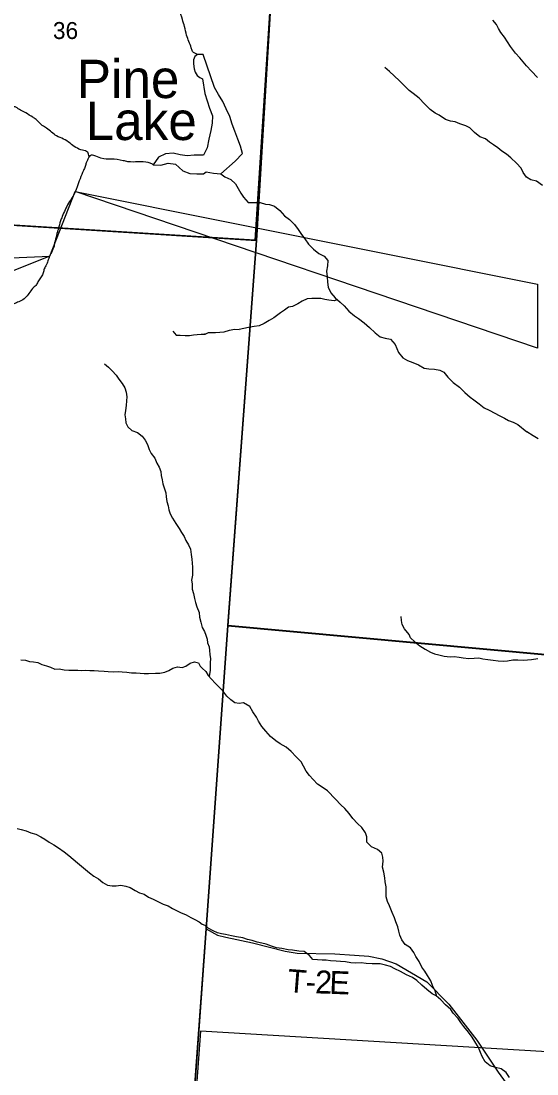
# Model space of a CAD drawing. Extents: x -13.1 to 43.1, y 0 to 22.
# Drawn here: x 6.242 to 7.517, y 14.849 to 17.45 of the extents above; entities that cross this region are included whole.
import ezdxf

# ---------------------------------------------------------------- set-up
doc = ezdxf.new("R2010")
doc.units = 0
for name, color, linetype in [('GM_X_Corporation', 7, 'Continuous'), ('GM_X_Minor_Lake', 7, 'Continuous'), ('GM_X_Minor_Lake_Text', 7, 'Continuous'), ('GM_X_Minor_River', 7, 'Continuous'), ('GM_X_Section_Text', 7, 'Continuous'), ('GM_X_Township_Road', 7, 'Continuous'), ('GM_X_Township_Road_Text', 7, 'Continuous'), ('SH_Text', 7, 'Continuous')]:
    doc.layers.add(name, color=color, linetype=linetype)

msp = doc.modelspace()

# ---------------------------------------------------------------- linework, layer by layer
at = {"layer": 'GM_X_Corporation'}
for points in [[(7.0807, 20.9), (2.1, 20.9), (2.1, 14.1), (6.6193, 14.1), (6.6994, 15.2069), (6.7531, 15.956), (6.8236, 16.9075), (6.9509, 19.0179), (7.0108, 19.8446), (7.0164, 19.8954), (7.0617, 20.6133)], [(7.0804, 20.9), (2.1, 20.9), (2.1, 14.1), (6.619, 14.1), (6.6992, 15.2074), (6.7528, 15.9566), (6.8234, 16.908), (6.8365, 17.1257), (6.9507, 19.0184), (6.9616, 19.1692), (7.0106, 19.8452), (7.0162, 19.896), (7.0615, 20.6138)], [(7.0804, 20.9), (2.1, 20.9), (2.1, 17.2152), (2.1437, 17.2135), (2.8442, 17.1637), (3.8328, 17.0966), (4.4304, 17.0575), (6.8234, 16.908), (6.8365, 17.1257), (6.9507, 19.0184), (6.9616, 19.1692), (7.0106, 19.8452), (7.0162, 19.896), (7.0615, 20.6138)], [(8.9, 15.7487), (8.9, 20.9), (7.0804, 20.9), (7.0615, 20.6138), (7.0162, 19.896), (7.0106, 19.8452), (6.9616, 19.1692), (6.9507, 19.0184), (6.8365, 17.1257), (6.8234, 16.908), (6.7528, 15.9566), (7.8612, 15.855), (8.7782, 15.7572)], [(8.9, 15.7487), (8.9, 20.9), (7.0804, 20.9), (7.0615, 20.6138), (7.0162, 19.896), (7.0106, 19.8452), (6.9616, 19.1692), (6.9507, 19.0184), (6.8365, 17.1257), (6.8234, 16.908), (6.7528, 15.9566), (7.8612, 15.855), (8.7782, 15.7572)], [(8.9, 15.7481), (8.9, 20.9), (7.0807, 20.9), (7.0617, 20.6133), (7.0164, 19.8954), (7.0108, 19.8446), (6.9509, 19.0179), (6.8236, 16.9075), (6.7531, 15.956), (7.8614, 15.8545), (8.7784, 15.7567)], [(5.8912, 17.9717), (6.8837, 17.9051), (6.8193, 16.9086), (5.8169, 16.9715)], [(2.1, 17.2152), (2.1, 14.1), (6.619, 14.1), (6.6992, 15.2074), (6.7528, 15.9566), (6.8234, 16.908), (4.4304, 17.0575), (3.8328, 17.0966), (2.8442, 17.1637), (2.1437, 17.2135)], [(6.619, 14.1), (8.9, 14.1), (8.9, 15.7487), (8.7782, 15.7572), (7.8612, 15.855), (6.7528, 15.9566), (6.6992, 15.2074)], [(6.619, 14.1), (8.9, 14.1), (8.9, 15.7487), (8.7782, 15.7572), (7.8612, 15.855), (6.7528, 15.9566), (6.6992, 15.2074)], [(6.6193, 14.1), (8.9, 14.1), (8.9, 15.7481), (8.7784, 15.7567), (7.8614, 15.8545), (6.7531, 15.956), (6.6994, 15.2069)], [(6.623, 14.1), (7.7024, 14.1), (7.7762, 14.8894), (6.6851, 14.9543)]]:
    msp.add_lwpolyline(points, close=True, dxfattribs=at)
at = {"layer": 'GM_X_Minor_Lake'}
for points in [[(6.6918, 17.367), (6.6784, 17.3673), (6.6715, 17.3625), (6.6684, 17.3542), (6.6683, 17.3439), (6.67, 17.3321), (6.6722, 17.3238), (6.6774, 17.3154), (6.6834, 17.3103), (6.6905, 17.3068)], [(6.6926, 17.0727), (6.6996, 17.0777), (6.7177, 17.0738), (6.7359, 17.0721), (6.7709, 17.1037), (6.7891, 17.1225), (6.784, 17.1408), (6.7773, 17.1582), (6.7699, 17.178), (6.7639, 17.1955), (6.758, 17.2145), (6.7491, 17.2327), (6.7409, 17.251), (6.7296, 17.2685), (6.7199, 17.286), (6.6918, 17.367)], [(6.6905, 17.3068), (6.6964, 17.271), (6.7016, 17.2528), (6.7075, 17.2345), (6.7149, 17.2155), (6.714, 17.1974), (6.7109, 17.1799), (6.7062, 17.158), (6.7023, 17.1368), (6.6927, 17.119)], [(6.6927, 17.119), (6.6699, 17.1184), (6.6525, 17.117), (6.6351, 17.1195), (6.6177, 17.1234), (6.5988, 17.122), (6.5813, 17.1138), (6.5683, 17.095), (6.5872, 17.0941), (6.6054, 17.0992), (6.6236, 17.096), (6.6416, 17.0799), (6.659, 17.0737), (6.6764, 17.0728), (6.6926, 17.0727)]]:
    msp.add_lwpolyline(points, dxfattribs=at)
at = {"layer": 'GM_X_Minor_River'}
for p, q in [((7.4166, 17.4411), (7.408, 17.4518)), ((7.4218, 17.4316), (7.4166, 17.4411)), ((7.4275, 17.4213), (7.4218, 17.4316)), ((7.4365, 17.4099), (7.4275, 17.4213)), ((7.4439, 17.3985), (7.4365, 17.4099)), ((7.4511, 17.3874), (7.4439, 17.3985)), ((7.4638, 17.371), (7.4511, 17.3874)), ((7.4747, 17.3592), (7.4638, 17.371)), ((7.4822, 17.3489), (7.4747, 17.3592)), ((7.1526, 17.3249), (7.1409, 17.3352)), ((7.1635, 17.3146), (7.1526, 17.3249)), ((7.4909, 17.3394), (7.4822, 17.3489)), ((7.5033, 17.326), (7.4909, 17.3394)), ((7.5179, 17.3104), (7.5033, 17.326)), ((7.1774, 17.302), (7.1635, 17.3146)), ((7.1887, 17.2909), (7.1774, 17.302)), ((7.2011, 17.2787), (7.1887, 17.2909)), ((7.2109, 17.2706), (7.2011, 17.2787)), ((7.2256, 17.2592), (7.2109, 17.2706)), ((7.2391, 17.2451), (7.2256, 17.2592)), ((7.253, 17.2317), (7.2391, 17.2451)), ((7.2651, 17.2225), (7.253, 17.2317)), ((7.2749, 17.2171), (7.2651, 17.2225)), ((7.2903, 17.2064), (7.2749, 17.2171)), ((7.3032, 17.2022), (7.2903, 17.2064)), ((7.3145, 17.2013), (7.3032, 17.2022)), ((7.3262, 17.1959), (7.3145, 17.2013)), ((7.341, 17.1913), (7.3262, 17.1959)), ((7.3511, 17.1859), (7.341, 17.1913)), ((7.362, 17.1745), (7.3511, 17.1859)), ((7.3756, 17.1641), (7.362, 17.1745)), ((7.3892, 17.1587), (7.3756, 17.1641)), ((7.3994, 17.1511), (7.3892, 17.1587)), ((7.4092, 17.1438), (7.3994, 17.1511)), ((7.4201, 17.1365), (7.4092, 17.1438)), ((7.4299, 17.1285), (7.4201, 17.1365)), ((7.4416, 17.1212), (7.4299, 17.1285)), ((7.4521, 17.1124), (7.4416, 17.1212)), ((7.466, 17.0991), (7.4521, 17.1124)), ((7.4777, 17.0861), (7.466, 17.0991)), ((7.4829, 17.0754), (7.4777, 17.0861)), ((7.4908, 17.0644), (7.4829, 17.0754)), ((7.5013, 17.0579), (7.4908, 17.0644)), ((7.5153, 17.0544), (7.5013, 17.0579)), ((7.53, 17.0437), (7.5153, 17.0544)), ((6.803, 17.0014), (6.8329, 17.0019)), ((6.8329, 17.0019), (6.8461, 16.9973)), ((6.8461, 16.9973), (6.8559, 16.9964)), ((6.8559, 16.9964), (6.8684, 16.993)), ((6.8684, 16.993), (6.8812, 16.9822)), ((6.8812, 16.9822), (6.8929, 16.9685)), ((6.8929, 16.9685), (6.9053, 16.9593)), ((6.9053, 16.9593), (6.9173, 16.9471)), ((6.9173, 16.9471), (6.9263, 16.9349)), ((6.9263, 16.9349), (6.9346, 16.9227)), ((6.9346, 16.9227), (6.9428, 16.9121)), ((6.9428, 16.9121), (6.9526, 16.8991)), ((6.9526, 16.8991), (6.9642, 16.8861)), ((6.9642, 16.8861), (6.9778, 16.8754)), ((6.9778, 16.8754), (6.9906, 16.8693)), ((6.9906, 16.8693), (7, 16.8582)), ((7, 16.8582), (6.9995, 16.8449)), ((6.9995, 16.8449), (6.9971, 16.8317)), ((6.9971, 16.8317), (6.9982, 16.818)), ((6.9982, 16.818), (6.9988, 16.8047)), ((6.9988, 16.8047), (7.0006, 16.7922)), ((7.0006, 16.7922), (7.0074, 16.7789)), ((7.0074, 16.7789), (7.0183, 16.7659)), ((6.9364, 16.7577), (6.9261, 16.7513)), ((6.9486, 16.7633), (6.9364, 16.7577)), ((6.9603, 16.7648), (6.9486, 16.7633)), ((6.9826, 16.7646), (6.9603, 16.7648)), ((6.9928, 16.7619), (6.9826, 16.7646)), ((7.0027, 16.7603), (6.9928, 16.7619)), ((7.0155, 16.7587), (7.0027, 16.7603)), ((7.0234, 16.7615), (7.0155, 16.7587)), ((7.0183, 16.7659), (7.0303, 16.7556)), ((7.0303, 16.7556), (7.0401, 16.7464)), ((6.8832, 16.7289), (6.8668, 16.7165)), ((6.8927, 16.7356), (6.8832, 16.7289)), ((6.9026, 16.7428), (6.8927, 16.7356)), ((6.9124, 16.745), (6.9026, 16.7428)), ((6.9261, 16.7513), (6.9124, 16.745)), ((7.0401, 16.7464), (7.0521, 16.7335)), ((7.0521, 16.7335), (7.0656, 16.7216)), ((6.8428, 16.7026), (6.8307, 16.6973)), ((6.8554, 16.7105), (6.8428, 16.7026)), ((6.8668, 16.7165), (6.8554, 16.7105)), ((7.0656, 16.7216), (7.0754, 16.7147)), ((7.0754, 16.7147), (7.0898, 16.704)), ((7.0898, 16.704), (7.1029, 16.6925)), ((6.8041, 16.6926), (6.781, 16.6877)), ((6.8182, 16.6955), (6.8041, 16.6926)), ((6.8307, 16.6973), (6.8182, 16.6955)), ((7.1029, 16.6925), (7.1172, 16.6796)), ((7.1172, 16.6796), (7.1289, 16.67)), ((7.1289, 16.67), (7.1414, 16.6669)), ((7.1414, 16.6669), (7.1546, 16.6641)), ((7.1546, 16.6641), (7.1662, 16.6508)), ((7.1662, 16.6508), (7.1703, 16.6413)), ((7.1703, 16.6413), (7.1748, 16.6314)), ((7.1748, 16.6314), (7.1849, 16.6177)), ((7.1849, 16.6177), (7.197, 16.6111)), ((7.197, 16.6111), (7.2102, 16.6061)), ((7.2102, 16.6061), (7.2242, 16.6007)), ((7.2242, 16.6007), (7.2382, 16.5927)), ((7.2382, 16.5927), (7.2495, 16.5911)), ((7.2495, 16.5911), (7.2631, 16.5902)), ((7.2631, 16.5902), (7.2764, 16.5875)), ((7.2764, 16.5875), (7.2862, 16.5825)), ((7.2862, 16.5825), (7.2963, 16.5703)), ((7.2963, 16.5703), (7.3098, 16.5569)), ((7.3098, 16.5569), (7.3249, 16.5454)), ((7.3249, 16.5454), (7.3384, 16.5321)), ((7.3384, 16.5321), (7.3512, 16.5206)), ((7.3512, 16.5206), (7.361, 16.5145)), ((7.361, 16.5145), (7.3735, 16.5045)), ((7.3735, 16.5045), (7.3863, 16.4946)), ((7.3863, 16.4946), (7.3987, 16.4885)), ((7.3987, 16.4885), (7.4123, 16.4812)), ((7.4123, 16.4812), (7.4229, 16.4754)), ((7.4229, 16.4754), (7.4361, 16.4692)), ((7.4361, 16.4692), (7.4466, 16.4635)), ((7.4466, 16.4635), (7.4576, 16.4592)), ((7.4576, 16.4592), (7.4693, 16.4535)), ((7.4693, 16.4535), (7.4915, 16.4352)), ((7.5072, 16.4255), (7.4915, 16.4352)), ((7.5192, 16.4175), (7.5072, 16.4255)), ((7.182, 15.9694), (7.1813, 15.9788)), ((7.1835, 15.9591), (7.182, 15.9694)), ((7.1891, 15.9481), (7.1835, 15.9591)), ((7.2007, 15.9344), (7.1891, 15.9481)), ((7.2046, 15.9264), (7.2007, 15.9344))]:
    msp.add_line(p, q, dxfattribs=at)
for points in [[(6.7359, 17.0721), (6.7457, 17.0651), (6.7605, 17.0587), (6.7719, 17.0481), (6.7787, 17.036), (6.7848, 17.025), (6.792, 17.0152), (6.803, 17.0014)], [(6.6174, 16.6842), (6.6255, 16.6742), (6.6353, 16.674), (6.6474, 16.673), (6.6584, 16.6732), (6.6679, 16.6746), (6.6774, 16.6755), (6.6872, 16.6765), (6.697, 16.676), (6.6955, 16.6764)], [(6.697, 16.676), (6.7049, 16.6807), (6.7223, 16.6807), (6.7333, 16.6812), (6.7439, 16.6823), (6.7567, 16.6862), (6.7692, 16.6888), (6.781, 16.6877)], [(6.4481, 16.6029), (6.4578, 16.5947), (6.4675, 16.5855), (6.4768, 16.5751), (6.4838, 16.5651), (6.4923, 16.5547), (6.4982, 16.544), (6.5018, 16.5333), (6.5031, 16.5219), (6.5026, 16.5113), (6.502, 16.5003), (6.4999, 16.4875), (6.4986, 16.4769), (6.5, 16.4674), (6.5006, 16.4571), (6.5057, 16.4472), (6.5158, 16.4387)], [(6.5158, 16.4387), (6.5296, 16.4336), (6.5417, 16.4247), (6.5491, 16.4148), (6.5543, 16.4037), (6.5587, 16.3915), (6.5639, 16.3819), (6.5725, 16.37), (6.5773, 16.3574), (6.5833, 16.3475), (6.5873, 16.3368), (6.588, 16.3269), (6.5905, 16.3166), (6.5923, 16.3064), (6.5963, 16.2942), (6.5996, 16.2842), (6.601, 16.2747), (6.602, 16.2633), (6.6057, 16.2526), (6.6075, 16.2428), (6.6108, 16.2325), (6.6159, 16.2218), (6.6249, 16.2083), (6.6327, 16.1965), (6.6387, 16.1865), (6.645, 16.1766), (6.6495, 16.167), (6.6562, 16.1559), (6.6606, 16.1452), (6.6627, 16.1323), (6.6641, 16.1209), (6.6648, 16.111), (6.6658, 16.1007), (6.6656, 16.0905), (6.6659, 16.081), (6.6635, 16.0689), (6.6645, 16.0594), (6.6647, 16.0468), (6.668, 16.0354), (6.6709, 16.0232), (6.6731, 16.0133), (6.6764, 16.0026), (6.6823, 15.9885), (6.6826, 15.9769), (6.686, 15.9652), (6.6895, 15.9514)], [(6.6895, 15.9514), (6.6955, 15.9419), (6.699, 15.9325), (6.7015, 15.923), (6.7028, 15.9135), (6.7071, 15.904), (6.7076, 15.8945), (6.7089, 15.885), (6.7102, 15.8747), (6.7093, 15.8652), (6.7093, 15.8553), (6.7097, 15.8458), (6.7076, 15.8363), (6.7066, 15.8305)], [(7.2046, 15.9264), (7.2148, 15.9162), (7.2272, 15.9067), (7.2401, 15.8979), (7.2537, 15.8904), (7.2636, 15.8866), (7.2738, 15.8839), (7.2874, 15.8805), (7.3018, 15.8793), (7.3124, 15.8801), (7.3241, 15.8786), (7.3343, 15.8766), (7.3483, 15.8755), (7.3612, 15.8762), (7.3733, 15.8766), (7.3831, 15.8743), (7.3952, 15.8728), (7.4081, 15.8709), (7.4206, 15.869), (7.4338, 15.8686), (7.4437, 15.8694), (7.4573, 15.8716), (7.4694, 15.8716), (7.4827, 15.8709), (7.4933, 15.872), (7.5031, 15.8727), (7.519, 15.8754)], [(6.2415, 15.8722), (6.2529, 15.871), (6.2627, 15.8674), (6.2726, 15.8673), (6.2832, 15.8656), (6.2934, 15.8606), (6.3048, 15.8566), (6.315, 15.8535), (6.3256, 15.8491), (6.3362, 15.8494), (6.3487, 15.8469), (6.3598, 15.846), (6.3704, 15.8459), (6.3826, 15.8465), (6.3924, 15.8456), (6.4019, 15.8459), (6.4118, 15.8458), (6.4225, 15.8452), (6.4338, 15.8443), (6.4475, 15.8438), (6.4574, 15.8429), (6.4695, 15.842), (6.4817, 15.8426), (6.4923, 15.8421), (6.5037, 15.8412), (6.5147, 15.8399), (6.5265, 15.8397), (6.5364, 15.8388), (6.5466, 15.8383), (6.5573, 15.8382), (6.5744, 15.8387), (6.5847, 15.8386), (6.5972, 15.8411), (6.6072, 15.8455), (6.6175, 15.8511), (6.6286, 15.8544), (6.6399, 15.8527), (6.6495, 15.856), (6.6595, 15.8638), (6.6705, 15.8671), (6.6807, 15.8643), (6.6847, 15.8562), (6.6892, 15.851)], [(6.6892, 15.851), (6.699, 15.8428), (6.7041, 15.8333), (6.7128, 15.8238), (6.7218, 15.8143), (6.7233, 15.8122)], [(7.2691, 15.04), (7.2654, 15.0544), (7.2586, 15.0673), (7.2541, 15.079), (7.2465, 15.0919), (7.2393, 15.1026), (7.2325, 15.1128), (7.2253, 15.1264), (7.217, 15.139), (7.2128, 15.1488), (7.2038, 15.1606), (7.1913, 15.1689), (7.1826, 15.1799), (7.1777, 15.1917), (7.1758, 15.2016), (7.1731, 15.2118), (7.1682, 15.2247), (7.1644, 15.2345), (7.1588, 15.2474), (7.152, 15.2641), (7.1474, 15.2744), (7.1444, 15.2861), (7.1437, 15.2971), (7.1444, 15.3111), (7.1418, 15.3237), (7.1407, 15.3331), (7.138, 15.3472), (7.135, 15.3597), (7.1365, 15.3748), (7.1361, 15.3843), (7.1335, 15.3946), (7.1225, 15.4033), (7.1081, 15.4101), (7.096, 15.4211), (7.0961, 15.4348), (7.0934, 15.4442), (7.084, 15.4575), (7.073, 15.4674), (7.0616, 15.4795), (7.0529, 15.492), (7.0416, 15.5042), (7.0325, 15.5137), (7.0193, 15.5277), (6.9992, 15.5478), (6.9886, 15.5554), (6.9746, 15.5645), (6.9637, 15.5759), (6.955, 15.5858), (6.9467, 15.5964), (6.9402, 15.6089), (6.9342, 15.6195), (6.9217, 15.6324), (6.9096, 15.6457), (6.8967, 15.6559), (6.882, 15.6643), (6.8714, 15.6715), (6.8585, 15.6825), (6.8468, 15.6954), (6.837, 15.7068), (6.829, 15.7201), (6.8234, 15.7303), (6.815, 15.7436), (6.8075, 15.7565), (6.792, 15.7652), (6.7806, 15.7637), (6.7704, 15.7652), (6.7602, 15.7728), (6.7503, 15.7823), (6.7409, 15.7956), (6.7284, 15.8077), (6.7233, 15.8122)], [(6.2322, 15.4554), (6.2424, 15.4526), (6.2546, 15.449), (6.2663, 15.4447), (6.2784, 15.4411), (6.2909, 15.4349), (6.3007, 15.4291), (6.312, 15.4213), (6.3233, 15.4147), (6.335, 15.4073), (6.3486, 15.3973), (6.3599, 15.3888), (6.3711, 15.3795), (6.3813, 15.3707), (6.3911, 15.3618), (6.4012, 15.3541), (6.4114, 15.3456), (6.4223, 15.3375), (6.4333, 15.3305), (6.4438, 15.322), (6.4555, 15.3154), (6.4669, 15.3134), (6.4768, 15.3136), (6.4889, 15.3154), (6.5007, 15.3129), (6.512, 15.309), (6.5241, 15.302), (6.5347, 15.2966), (6.5464, 15.2926), (6.5566, 15.2856), (6.5683, 15.2802), (6.5804, 15.2751), (6.5933, 15.2681), (6.6054, 15.2637), (6.6163, 15.2575), (6.6261, 15.2525), (6.6359, 15.2478), (6.6499, 15.2415), (6.6616, 15.2349), (6.6718, 15.2306), (6.682, 15.2244), (6.6895, 15.2192), (6.6958, 15.2162)], [(7.0948, 15.1216), (7.0823, 15.1231), (7.0683, 15.1228), (7.0565, 15.1232), (7.044, 15.1254), (7.0312, 15.1262), (7.0202, 15.127), (7.0062, 15.1285), (6.9956, 15.13), (6.9858, 15.1297), (6.9748, 15.1308), (6.9627, 15.1316), (6.9544, 15.1414), (6.9419, 15.1509), (6.9283, 15.1517), (6.9131, 15.1544), (6.9018, 15.1555), (6.8863, 15.1589), (6.8734, 15.1604), (6.8609, 15.1646), (6.8473, 15.1696), (6.8367, 15.1715), (6.8257, 15.1745), (6.8128, 15.1787), (6.8019, 15.1806), (6.7901, 15.1848), (6.7746, 15.1874), (6.7618, 15.1897), (6.7474, 15.1931), (6.7372, 15.1947), (6.7273, 15.197), (6.7171, 15.2023), (6.7042, 15.2091), (6.6958, 15.2162)], [(7.4488, 14.8401), (7.4405, 14.8526), (7.4284, 14.8613), (7.414, 14.8647), (7.4008, 14.8685), (7.3887, 14.8788), (7.3811, 14.892), (7.3773, 14.9019), (7.372, 14.914), (7.363, 14.9292), (7.3565, 14.9394), (7.3471, 14.9516), (7.3357, 14.966), (7.3286, 14.9762), (7.3221, 14.9861), (7.3096, 14.9986), (7.3036, 15.0081), (7.2907, 15.0199), (7.279, 15.032), (7.2673, 15.0415), (7.2574, 15.0468), (7.2446, 15.0574), (7.2325, 15.0684), (7.2196, 15.0794), (7.2094, 15.0874), (7.1946, 15.0935), (7.1795, 15.1022), (7.1655, 15.1087), (7.1545, 15.114), (7.1424, 15.1178), (7.1296, 15.1205), (7.1197, 15.1212), (7.1095, 15.1208), (7.0948, 15.1216)]]:
    msp.add_lwpolyline(points, dxfattribs=at)
for points in [[(6.6784, 17.3673), (6.6659, 17.3751), (6.6626, 17.3839), (6.6511, 17.4147), (6.646, 17.4363), (6.6408, 17.4538), (6.6283, 17.5035), (6.6232, 17.5281), (6.618, 17.5449), (6.6108, 17.585), (6.6094, 17.6002), (6.6075, 17.6082), (6.6038, 17.6226), (6.6012, 17.6234), (6.6009, 17.6272), (6.5866, 17.6338), (6.5651, 17.6413), (6.5312, 17.6508), (6.5222, 17.6585), (6.4823, 17.6757), (6.4642, 17.6813), (6.4254, 17.6943), (6.4179, 17.7001), (6.3837, 17.7153), (6.3667, 17.7212), (6.3291, 17.7365), (6.3246, 17.7423), (6.2994, 17.7562), (6.2866, 17.764), (6.2734, 17.7695), (6.2471, 17.7823), (6.2343, 17.7882), (6.2162, 17.7922), (6.1872, 17.8043), (6.1767, 17.8117), (6.1669, 17.8171), (6.1489, 17.8313), (6.141, 17.8383), (6.123, 17.8495), (6.1128, 17.8568), (6.0997, 17.8623), (6.0673, 17.8783), (6.0409, 17.8866), (6.0346, 17.892), (6.0075, 17.9067), (5.9977, 17.9114), (5.9902, 17.9179), (5.9642, 17.9315), (5.9537, 17.9374), (5.9432, 17.9417), (5.9278, 17.9563), (5.9161, 17.9647), (5.9128, 17.9716), (5.8986, 17.9896), (5.8918, 17.9957), (5.887, 18.0049), (5.8746, 18.019), (5.8701, 18.0263), (5.8544, 18.0458)], [(6.4101, 17.1149), (6.4067, 17.1259), (6.3939, 17.1306), (6.3631, 17.148), (6.3469, 17.1585), (6.33, 17.1663), (6.3052, 17.1852), (6.2947, 17.1917), (6.2793, 17.2067), (6.2711, 17.2125), (6.2538, 17.223), (6.247, 17.2268), (6.241, 17.2296), (6.2293, 17.2369), (6.2218, 17.24), (6.2154, 17.2439), (6.2116, 17.2451), (6.209, 17.2463), (6.2015, 17.246), (6.1943, 17.2457), (6.1852, 17.2451), (6.1735, 17.2404), (6.1682, 17.2359), (6.1624, 17.2265), (6.1362, 17.2038), (6.1097, 17.1902), (6.1036, 17.1801), (6.074, 17.1522), (6.0588, 17.1418), (6.016, 17.1186), (6.0102, 17.1084), (5.9925, 17.1026), (5.9678, 17.0883), (5.953, 17.0805), (5.9492, 17.0741), (5.9336, 17.0558), (5.9249, 17.0454), (5.9222, 17.0371), (5.9129, 17.0138), (5.9114, 17.0044), (5.9109, 16.9976), (5.9105, 16.9824), (5.9134, 16.9771), (5.9142, 16.9726), (5.916, 16.9597), (5.9167, 16.954), (5.9181, 16.9411), (5.9185, 16.9377)], [(6.5683, 17.095), (6.5613, 17.0987), (6.5564, 17.1003), (6.5062, 17.1025), (6.4946, 17.105), (6.4644, 17.1088), (6.4395, 17.1114), (6.4101, 17.1149), (6.4089, 17.1122), (6.4032, 17.0998), (6.4005, 17.0908), (6.3962, 17.0806), (6.3805, 17.04), (6.3705, 17.0171), (6.3594, 17.0002), (6.3437, 16.9668), (6.3395, 16.9563), (6.3341, 16.9363), (6.3318, 16.9292), (6.3275, 16.9111), (6.3256, 16.9043), (6.3236, 16.8941), (6.3171, 16.8783), (6.314, 16.8723), (6.3094, 16.8599), (6.3075, 16.8546), (6.3021, 16.8426), (6.2994, 16.8374), (6.2971, 16.8279), (6.2853, 16.8085), (6.2799, 16.7987), (6.2731, 16.7916), (6.2548, 16.7684), (6.2434, 16.7595), (6.2305, 16.754), (6.2063, 16.7453), (6.1779, 16.7408), (6.173, 16.7371), (6.1617, 16.7335), (6.1496, 16.731), (6.1269, 16.7222), (6.1151, 16.7201), (6.1019, 16.7177)]]:
    msp.add_spline(points, degree=3, dxfattribs=at)
at = {"layer": 'GM_X_Township_Road'}
msp.add_lwpolyline([(6.6994, 15.2069), (6.7277, 15.1918), (6.7478, 15.187), (6.8135, 15.1728), (6.8943, 15.1522), (6.9242, 15.1469), (7.017, 15.1455), (7.0662, 15.1425), (7.1014, 15.1401), (7.1332, 15.1329), (7.1686, 15.1206), (7.2442, 15.0762), (7.2987, 15.0212), (7.3684, 14.9325), (7.4211, 14.8528), (7.4576, 14.8021)], dxfattribs=at)
at = {"layer": 'SH_Text'}
msp.add_line((6.3129, 16.8693), (6.3758, 17.0288), dxfattribs=at)
for points in [[(7.5178, 16.6422), (6.3758, 17.0288), (7.5178, 16.7996)], [(5.841, 16.8489), (6.3129, 16.8693), (5.841, 16.6815)]]:
    msp.add_lwpolyline(points, close=True, dxfattribs=at)

# ---------------------------------------------------------------- texts
at = {"layer": 'GM_X_Minor_Lake_Text'}
for s, p in [('Pine', (6.3799, 17.2597)), ('Lake', (6.4018, 17.156))]:
    msp.add_text(s, height=0.09469, rotation=359.9984, dxfattribs=at).set_placement(p)
at = {"layer": 'GM_X_Section_Text'}
msp.add_text('36', height=0.04186, rotation=0, dxfattribs=at).set_placement((6.3209, 17.4056))
at = {"layer": 'GM_X_Township_Road_Text'}
for s, rotation, p in [('T', 355.5125, (6.8986, 15.0516)), ('2', 358.7822, (6.9681, 15.0478)), ('E', 357.5222, (7.0028, 15.047)), ('-', 359.1336, (6.9449, 15.0481))]:
    msp.add_text(s, height=0.0568, rotation=rotation, dxfattribs=at).set_placement(p)

doc.saveas('drawing.dxf')
